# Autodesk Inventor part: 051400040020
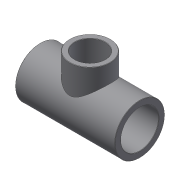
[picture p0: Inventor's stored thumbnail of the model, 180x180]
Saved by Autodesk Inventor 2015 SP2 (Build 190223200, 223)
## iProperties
Created: 2017-10
Part Number: 051400040020
Material: Generic
Description: PLASSON REDUCER TEE - CEMENT PVC 40-20-40
Document SubType Name: Modeling
Designer: KIM
Density: 1 g/cm^3
Appearance: Default
Author: KIM
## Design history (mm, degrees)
derived "051400.ipt"
feature "Solid1::051400.ipt"
feature "Solid2::051400.ipt"
tag "TaggingFeature1"
body "Solid1"
other parameters: "d0" = 99, "d2" = 26, "d5" = 36, "d7" = 0.4, "d8" = 26, "d9" = 38, "d12" = 18, "d23" = 16, "d24" = 0.4, "d26" = 0, "d30" = 0, "d32" = 0, "H_" = 99, "l_" = 26, "Z_" = 14, "l_1" = 16, "Z_1" = 12.5, "H_1" = 63
